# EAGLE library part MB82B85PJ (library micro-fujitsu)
MICROCONTROLLER/MEMORY DEVICE
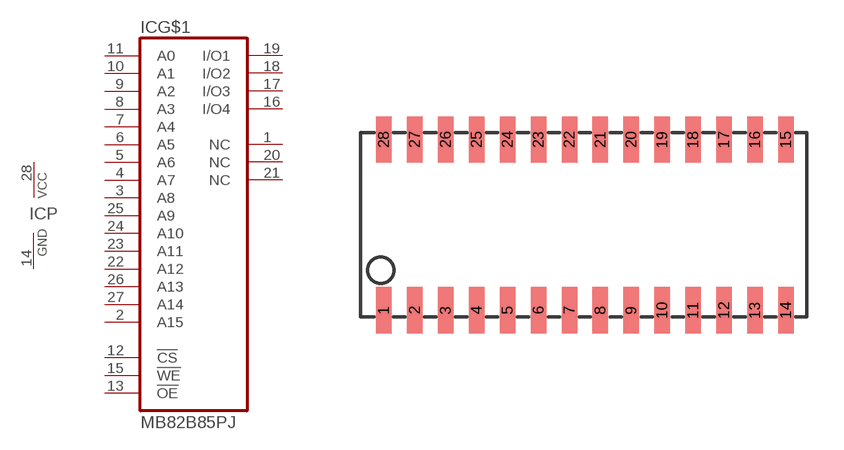
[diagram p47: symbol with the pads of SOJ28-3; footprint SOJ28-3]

Designator prefix IC; gates G$1=MB82B85 P=VCC-GND

## MB82B85PJ (OC_FARNELL: unknown; OC_NEWARK: unknown)  [SOJ28-3]
1  G$1:NC  nc
2  G$1:A15  in
3  G$1:A8  in
4  G$1:A7  in
5  G$1:A6  in
6  G$1:A5  in
7  G$1:A4  in
8  G$1:A3  in
9  G$1:A2  in
10  G$1:A1  in
11  G$1:A0  in
12  G$1:!CS  in
13  G$1:!OE  in
14  P:GND  pwr
15  G$1:!WE  in
16  G$1:I/O4  nc
17  G$1:I/O3
18  G$1:I/O2
19  G$1:I/O1
20  G$1:NC  nc
21  G$1:NC  nc
22  G$1:A12  in
23  G$1:A11  in
24  G$1:A10  in
25  G$1:A9  in
26  G$1:A13  in
27  G$1:A14  in
28  P:VCC  pwr

## Footprint SOJ28-3 (pad centres in mm)
Small Outline J-Bend
smd 0.635 x 1.905: 1 -8.255,-3.505; 2 -6.985,-3.505; 3 -5.715,-3.505; 4 -4.445,-3.505; 5 -3.175,-3.505; 6 -1.905,-3.505; 7 -0.635,-3.505; 8 0.635,-3.505; 9 1.905,-3.505; 10 3.175,-3.505; 11 4.445,-3.505; 12 5.715,-3.505; 13 6.985,-3.505; 14 8.255,-3.505; 15 8.255,3.505; 16 6.985,3.505; 17 5.715,3.505; 18 4.445,3.505; 19 3.175,3.505; 20 1.905,3.505; 21 0.635,3.505; 22 -0.635,3.505; 23 -1.905,3.505; 24 -3.175,3.505; 25 -4.445,3.505; 26 -5.715,3.505; 27 -6.985,3.505; 28 -8.255,3.505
